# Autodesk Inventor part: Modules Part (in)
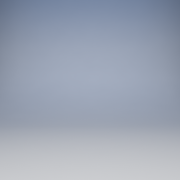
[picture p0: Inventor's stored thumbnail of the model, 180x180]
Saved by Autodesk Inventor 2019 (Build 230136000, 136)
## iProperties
Created: 2014-08
Part Number: Modules Part (in)
Material: Generic
Document SubType Name: Modeling
Designer: Wally
Manufacturer: Standard
Standards Organization: Custom
Density: 1 g/cm^3
Appearance: Default
Author: Wally
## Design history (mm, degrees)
node "Sketch1"
